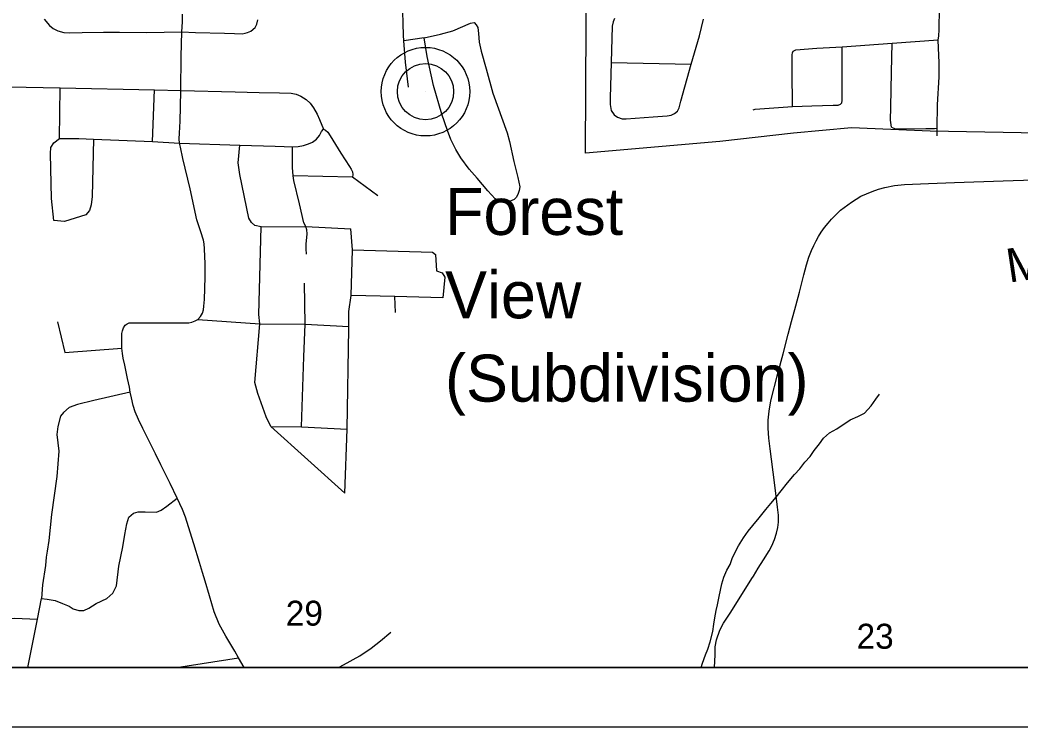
# Model space of a CAD drawing. Extents: x 0 to 34, y 0 to 22.
# Drawn here: x 5.55 to 7.23, y 14 to 15.187 of the extents above; entities that cross this region are included whole.
import ezdxf

# ---------------------------------------------------------------- set-up
doc = ezdxf.new("R2010")
doc.units = 0
for name, color, linetype in [('GM_X_City_Street', 7, 'Continuous'), ('GM_X_Corporation', 7, 'Continuous'), ('GM_X_County_Road', 7, 'Continuous'), ('GM_X_Minor_River', 7, 'Continuous'), ('GM_X_Section_Text', 7, 'Continuous'), ('GM_X_Township_Road', 7, 'Continuous'), ('GM_X_Township_Road_Text', 7, 'Continuous'), ('GM_X_Unincorporated', 7, 'Continuous'), ('GM_X_Unincorporated_Location', 7, 'Continuous'), ('GM_X_Unincorporated_Text', 7, 'Continuous'), ('SH_Data', 7, 'Continuous')]:
    doc.layers.add(name, color=color, linetype=linetype)

msp = doc.modelspace()

# ---------------------------------------------------------------- linework, layer by layer
at = {"layer": 'GM_X_City_Street'}
msp.add_line((6.5431, 15.1162), (6.6771, 15.1129), dxfattribs=at)
for points in [[(7.0902, 14.9926), (7.0903, 15.0058), (7.0908, 15.0451), (7.0937, 15.092), (7.0936, 15.1157), (7.0925, 15.1403), (7.092, 15.1542), (7.0932, 15.1603), (7.0936, 15.1715), (7.0951, 15.2437)], [(6.5485, 15.19), (6.546, 15.1845), (6.5446, 15.177), (6.5431, 15.1162), (6.5419, 15.0761), (6.5413, 15.0566), (6.5411, 15.0454), (6.5431, 15.0352), (6.5478, 15.028), (6.5538, 15.024), (6.5615, 15.0216), (6.5683, 15.0213), (6.6132, 15.0248), (6.6367, 15.0265), (6.6435, 15.0276), (6.6494, 15.0301), (6.6542, 15.0345), (6.6572, 15.0401), (6.6601, 15.0508), (6.6771, 15.1129), (6.6911, 15.1605), (6.6979, 15.1888)], [(6.8487, 15.1349), (6.8532, 15.137), (6.8883, 15.1399), (6.9308, 15.1422), (7.0146, 15.1487), (7.092, 15.1542)], [(6.8472, 15.0419), (6.8469, 15.1017), (6.8471, 15.1289), (6.8474, 15.1321), (6.8487, 15.1349)], [(6.9283, 15.0462), (6.9302, 15.0485), (6.9309, 15.052), (6.9309, 15.0664), (6.9308, 15.1422)], [(7.0135, 15.0076), (7.0122, 15.0193), (7.0125, 15.041), (7.014, 15.0997), (7.0146, 15.1487)], [(6.7813, 15.0363), (6.7846, 15.0378), (6.8472, 15.0419), (6.8799, 15.0431), (6.9156, 15.0445), (6.9241, 15.0443), (6.9283, 15.0462)], [(7.0135, 15.0076), (7.0186, 15.0052), (7.0275, 15.0045), (7.0367, 15.0047), (7.0715, 15.005), (7.0859, 15.005), (7.0903, 15.0058)]]:
    msp.add_lwpolyline(points, dxfattribs=at)
at = {"layer": 'GM_X_Corporation'}
for points in [[(4.5503, 14.1), (8.9, 14.1), (8.9, 15.6953), (8.4164, 15.7046), (8.4088, 15.7047), (8.2556, 15.7096), (8.2436, 15.7079), (8.2379, 15.708), (7.8346, 15.7173), (7.3532, 15.7283), (7.2238, 15.7321), (7.2174, 15.7331), (7.1916, 15.7337), (7.0294, 15.7382), (6.9267, 15.7411), (6.8653, 15.7428), (6.8105, 15.7443), (6.4702, 15.7474), (5.7944, 15.7634), (5.6123, 15.7657), (5.6068, 15.7657), (5.6014, 15.7658), (5.4664, 15.7674)], [(7.2621, 14.9971), (7.0789, 15.0004), (6.9464, 15.0064), (6.8493, 14.9972), (6.7253, 14.9831), (6.5, 14.9635), (6.502, 15.3971)]]:
    msp.add_lwpolyline(points, dxfattribs=at)
at = {"layer": 'GM_X_County_Road'}
for points in [[(5.9264, 14.1), (5.9169, 14.1163), (5.9106, 14.1272), (5.8955, 14.1528), (5.8843, 14.1729), (5.8762, 14.1934), (5.8682, 14.2203), (5.8607, 14.2447), (5.8564, 14.2593), (5.8514, 14.2763), (5.842, 14.3074), (5.8331, 14.3361), (5.828, 14.3523), (5.8228, 14.3654), (5.814, 14.3843), (5.802, 14.4087), (5.7866, 14.4402), (5.7776, 14.4587), (5.7664, 14.4814), (5.7565, 14.5011), (5.749, 14.5166), (5.7435, 14.5295), (5.7401, 14.54), (5.7372, 14.553), (5.7351, 14.5622), (5.7338, 14.5706), (5.7307, 14.5851), (5.7258, 14.6074), (5.7234, 14.6192), (5.7222, 14.6272), (5.7211, 14.636), (5.721, 14.6549), (5.7211, 14.6607), (5.7219, 14.6653), (5.7235, 14.6705), (5.7266, 14.6746), (5.7299, 14.6769), (5.7335, 14.6785), (5.763, 14.6788), (5.8017, 14.6785), (5.8267, 14.6786), (5.8334, 14.679), (5.8387, 14.6799), (5.8444, 14.682), (5.8485, 14.6845), (5.853, 14.6892), (5.8564, 14.6948), (5.8579, 14.7004), (5.8589, 14.7067), (5.8598, 14.7177), (5.8611, 14.7557), (5.8607, 14.7781), (5.8596, 14.8031), (5.859, 14.8114), (5.8581, 14.8177), (5.8536, 14.8315), (5.8468, 14.8519), (5.8357, 14.9038), (5.8236, 14.955), (5.8193, 14.974), (5.8178, 14.9803), (5.8175, 14.988), (5.8176, 14.9973), (5.8187, 15.0177), (5.8196, 15.0415), (5.8199, 15.0688), (5.8208, 15.1263), (5.822, 15.1672), (5.8227, 15.1841), (5.8226, 15.197)], [(6.7818, 14.2535), (6.79, 14.2668), (6.799, 14.2808), (6.808, 14.2957), (6.8126, 14.3044), (6.8172, 14.3151), (6.8205, 14.3256), (6.8227, 14.3353), (6.824, 14.3439), (6.8237, 14.3558), (6.822, 14.369), (6.817, 14.4104), (6.81, 14.4672), (6.8078, 14.4849), (6.8065, 14.5019), (6.8066, 14.5152), (6.8081, 14.5306), (6.811, 14.5478), (6.8229, 14.5934), (6.8318, 14.6269), (6.8404, 14.6598), (6.846, 14.6808), (6.8529, 14.7072), (6.859, 14.7301), (6.8667, 14.7595), (6.8711, 14.776), (6.8751, 14.7888), (6.8793, 14.8005), (6.8831, 14.8087), (6.887, 14.8166), (6.891, 14.8235), (6.8957, 14.8311), (6.9014, 14.839), (6.9071, 14.8464), (6.913, 14.8531), (6.9206, 14.8608), (6.9283, 14.8678), (6.9464, 14.8815), (6.9625, 14.8915), (6.9814, 14.8996), (6.9918, 14.9033), (7.0027, 14.9063), (7.0188, 14.9096), (7.0356, 14.9113), (7.0758, 14.9128), (7.1195, 14.9142), (7.2014, 14.9171), (7.3033, 14.9206)], [(6.7166, 14.1), (6.7173, 14.1213), (6.7177, 14.1348), (6.7199, 14.1463), (6.7252, 14.1625), (6.7315, 14.1745), (6.744, 14.1927), (6.7792, 14.2493), (6.7818, 14.2535)]]:
    msp.add_lwpolyline(points, dxfattribs=at)
at = {"layer": 'GM_X_Minor_River'}
msp.add_lwpolyline([(6.6939, 14.1), (6.6961, 14.1072), (6.7011, 14.121), (6.7051, 14.1309), (6.709, 14.1432), (6.7136, 14.1604), (6.7153, 14.1726), (6.7169, 14.1836), (6.7194, 14.1954), (6.7214, 14.205), (6.7242, 14.2191), (6.7263, 14.2298), (6.7287, 14.2405), (6.7323, 14.2516), (6.7373, 14.2635), (6.7425, 14.2731), (6.7464, 14.283), (6.7512, 14.2938), (6.7566, 14.3045), (6.7651, 14.3176), (6.7732, 14.3288), (6.7806, 14.3385), (6.7914, 14.3512), (6.8025, 14.3651), (6.811, 14.3756), (6.8203, 14.386), (6.8285, 14.3964), (6.8392, 14.41), (6.8511, 14.4239), (6.8596, 14.4336), (6.8681, 14.4448), (6.8771, 14.4544), (6.8841, 14.4641), (6.8926, 14.4757), (6.8996, 14.4853), (6.9097, 14.4939), (6.9217, 14.5009), (6.9446, 14.5158), (6.957, 14.5214), (6.9683, 14.527), (6.9794, 14.5393), (6.9875, 14.5505), (6.9938, 14.559)], dxfattribs=at)
at = {"layer": 'GM_X_Township_Road'}
for p, q in [((5.6164, 14.9882), (5.6175, 15.0734)), ((5.7724, 14.9834), (5.7756, 15.07)), ((5.9551, 14.8401), (6.0298, 14.8404)), ((6.0298, 14.8404), (6.1057, 14.8366)), ((6.1804, 14.6961), (6.1794, 14.723)), ((5.8128, 14.1), (5.9169, 14.1163))]:
    msp.add_line(p, q, dxfattribs=at)
for points in [[(6.1941, 15.1621), (6.1925, 15.2217), (6.1902, 15.2356), (6.1848, 15.2484), (6.1778, 15.2645), (6.1404, 15.3372), (6.1254, 15.3685), (6.1168, 15.3902), (6.1124, 15.4031), (6.1025, 15.4291), (6.0982, 15.4475), (6.0951, 15.5007), (6.095, 15.5036)], [(5.5903, 15.1885), (5.5997, 15.1779), (5.6059, 15.1731), (5.6136, 15.1692), (5.6234, 15.1666), (5.6323, 15.1657), (5.6544, 15.1661), (5.6901, 15.1667), (5.7171, 15.1667), (5.7623, 15.1666), (5.822, 15.1672), (5.8448, 15.1665), (5.8935, 15.1653), (5.9101, 15.1647), (5.9229, 15.1643), (5.9281, 15.1651), (5.9322, 15.1661), (5.9377, 15.1685), (5.945, 15.1745), (5.9478, 15.1806), (5.9492, 15.1875)], [(6.2286, 15.1576), (6.2563, 15.1634), (6.2767, 15.1692), (6.3067, 15.1819), (6.3125, 15.1829), (6.316, 15.1792), (6.3188, 15.1749), (6.3202, 15.1645), (6.321, 15.1502), (6.3244, 15.1351), (6.3329, 15.1056), (6.3444, 15.0646), (6.3683, 14.9977), (6.3723, 14.9833), (6.3794, 14.9499), (6.3863, 14.923), (6.3893, 14.9069), (6.3885, 14.9008), (6.3867, 14.8958), (6.3837, 14.8899), (6.38, 14.8859), (6.3722, 14.8823), (6.3616, 14.8808), (6.3546, 14.8833), (6.3479, 14.8872), (6.3355, 14.9005), (6.3177, 14.9215), (6.3046, 14.9366), (6.2905, 14.9558), (6.2818, 14.9699), (6.2736, 14.9866), (6.268, 15.002), (6.2586, 15.0293), (6.2447, 15.0773), (6.2338, 15.1262), (6.2286, 15.1576), (6.1944, 15.1523)], [(6.2025, 15.0745), (6.1975, 15.1165), (6.1944, 15.1523), (6.1941, 15.1621)], [(5.4856, 15.0765), (5.5316, 15.0751), (5.6175, 15.0734), (5.7756, 15.07), (5.8199, 15.0688)], [(5.8199, 15.0688), (5.9111, 15.0666), (5.9519, 15.0654), (5.986, 15.0651), (6.0054, 15.0646), (6.0138, 15.0627), (6.0218, 15.0595), (6.0307, 15.0538), (6.0372, 15.0475), (6.0429, 15.0396), (6.0489, 15.0293), (6.0532, 15.0204), (6.0597, 15.0041), (6.0631, 15.0026), (6.067, 14.9988), (6.0711, 14.9929), (6.089, 14.9636), (6.1035, 14.9415), (6.1062, 14.9371), (6.1085, 14.9325), (6.1088, 14.9277), (6.1083, 14.9232)], [(5.9935, 14.9748), (6.0074, 14.9741), (6.017, 14.9748), (6.0263, 14.9764), (6.0343, 14.9791), (6.0412, 14.9824), (6.0477, 14.9873), (6.0528, 14.9933), (6.0562, 15.0001), (6.0597, 15.0041)], [(5.6733, 14.9872), (5.671, 14.8907), (5.6695, 14.8767), (5.6665, 14.8676), (5.6604, 14.8604), (5.6248, 14.849), (5.607, 14.8508), (5.6029, 14.8876), (5.6012, 14.9631), (5.6019, 14.9733), (5.6067, 14.9809)], [(5.6067, 14.9809), (5.6164, 14.9882), (5.6487, 14.9885), (5.6733, 14.9872), (5.7724, 14.9834), (5.8178, 14.9803)], [(5.8178, 14.9803), (5.9189, 14.9771), (5.9787, 14.9755), (5.9935, 14.9748)], [(6.0958, 14.3927), (5.9713, 14.5045), (5.9635, 14.5211), (5.9496, 14.5599), (5.9445, 14.5783), (5.9525, 14.6773), (5.951, 14.6928), (5.9551, 14.8401), (5.9442, 14.8424), (5.9386, 14.8475), (5.9344, 14.8546), (5.919, 14.9281), (5.9165, 14.9477), (5.9189, 14.9771)], [(6.0298, 14.8404), (6.0265, 14.8465), (6.0195, 14.8788), (6.0101, 14.9176), (6.0089, 14.9257), (6.0076, 14.9396), (6.0074, 14.9741)], [(6.151, 14.8919), (6.1083, 14.9232), (6.0089, 14.9257)], [(6.0313, 14.7939), (6.0307, 14.8029), (6.0308, 14.8107), (6.0323, 14.8282), (6.0319, 14.8348), (6.0298, 14.8404)], [(6.1024, 14.6695), (6.1024, 14.6724), (6.1021, 14.6977), (6.1063, 14.7248), (6.1085, 14.8012), (6.1057, 14.8366)], [(6.1085, 14.8012), (6.2429, 14.7977), (6.248, 14.7936), (6.2493, 14.7659), (6.2589, 14.7629), (6.2635, 14.7553), (6.26, 14.7207), (6.1794, 14.723), (6.1063, 14.7248)], [(6.0227, 14.5041), (6.0267, 14.6216), (6.0288, 14.6766), (6.0277, 14.7451)], [(5.6128, 14.6803), (5.6255, 14.6287), (5.7211, 14.636)], [(5.8485, 14.6845), (5.9525, 14.6773), (6.0288, 14.6766), (6.1024, 14.6724)], [(6.0958, 14.3927), (6.0993, 14.5002), (6.1024, 14.6695)], [(5.7351, 14.5622), (5.6738, 14.5481), (5.6466, 14.5417), (5.6327, 14.5366), (5.6228, 14.5282), (5.6179, 14.5218), (5.6134, 14.5049), (5.6118, 14.4912), (5.6154, 14.4635), (5.6116, 14.4205), (5.6029, 14.357), (5.5981, 14.313), (5.5953, 14.2953), (5.5941, 14.2853)], [(5.9713, 14.5045), (6.0227, 14.5041), (6.0993, 14.5002)], [(5.5941, 14.2853), (5.5925, 14.2714), (5.5877, 14.2389), (5.586, 14.216), (5.5954, 14.2148), (5.6092, 14.2126), (5.6213, 14.2074), (5.6327, 14.203), (5.6395, 14.1983), (5.6487, 14.1957), (5.6569, 14.1957), (5.6653, 14.1997), (5.6781, 14.2074), (5.6957, 14.216), (5.7058, 14.2246), (5.7122, 14.2368), (5.7157, 14.2699), (5.7226, 14.3026), (5.7259, 14.3235), (5.7295, 14.341), (5.7328, 14.3522), (5.7406, 14.3593), (5.7485, 14.3613), (5.7602, 14.3616), (5.779, 14.3608), (5.7871, 14.3644), (5.7963, 14.371), (5.814, 14.3843)], [(5.5629, 14.1), (5.5793, 14.1812), (5.586, 14.216)], [(5.5088, 14.1), (5.5067, 14.1012), (5.495, 14.1059), (5.4683, 14.1095), (5.4565, 14.1127), (5.4483, 14.1177), (5.4441, 14.1224), (5.4417, 14.1278), (5.4411, 14.1344), (5.4425, 14.1395), (5.4448, 14.1438), (5.4501, 14.149), (5.4684, 14.1591), (5.4966, 14.1736), (5.5066, 14.1797), (5.5151, 14.1818), (5.5262, 14.1822), (5.5406, 14.1825), (5.5793, 14.1812)], [(6.085, 14.1), (6.0933, 14.1045), (6.1207, 14.1197), (6.14, 14.1324), (6.1553, 14.1446), (6.1726, 14.1593)]]:
    msp.add_lwpolyline(points, dxfattribs=at)
at = {"layer": 'GM_X_Unincorporated'}
for radius in [0.0744, 0.0472]:
    msp.add_circle((6.231, 15.067), radius, dxfattribs=at)
at = {"layer": 'GM_X_Unincorporated_Location'}
msp.add_line((6.231, 15.067), (6.231, 15.067), dxfattribs=at)
at = {"layer": 'SH_Data'}
msp.add_line((2, 14), (9, 14), dxfattribs=at)
msp.add_lwpolyline([(2.1, 20.9), (8.9, 20.9), (8.9, 14.1), (2.1, 14.1)], close=True, dxfattribs=at)

# ---------------------------------------------------------------- texts
at = {"layer": 'GM_X_Section_Text'}
for s, p in [('29', (5.9964, 14.1702)), ('23', (6.9551, 14.1315))]:
    msp.add_text(s, height=0.04186, rotation=0, dxfattribs=at).set_placement(p)
at = {"layer": 'GM_X_Township_Road_Text'}
msp.add_text('M', height=0.0568, rotation=8.4304, dxfattribs=at).set_placement((7.211, 14.7461))
at = {"layer": 'GM_X_Unincorporated_Text'}
for s, height, p in [('Forest', 0.07898, (6.2639, 14.8264)), ('View', 0.07898, (6.2639, 14.6864)), ('(Subdivision)', 0.078977, (6.2639, 14.5464))]:
    msp.add_text(s, height=height, rotation=0, dxfattribs=at).set_placement(p)

doc.saveas('drawing.dxf')
